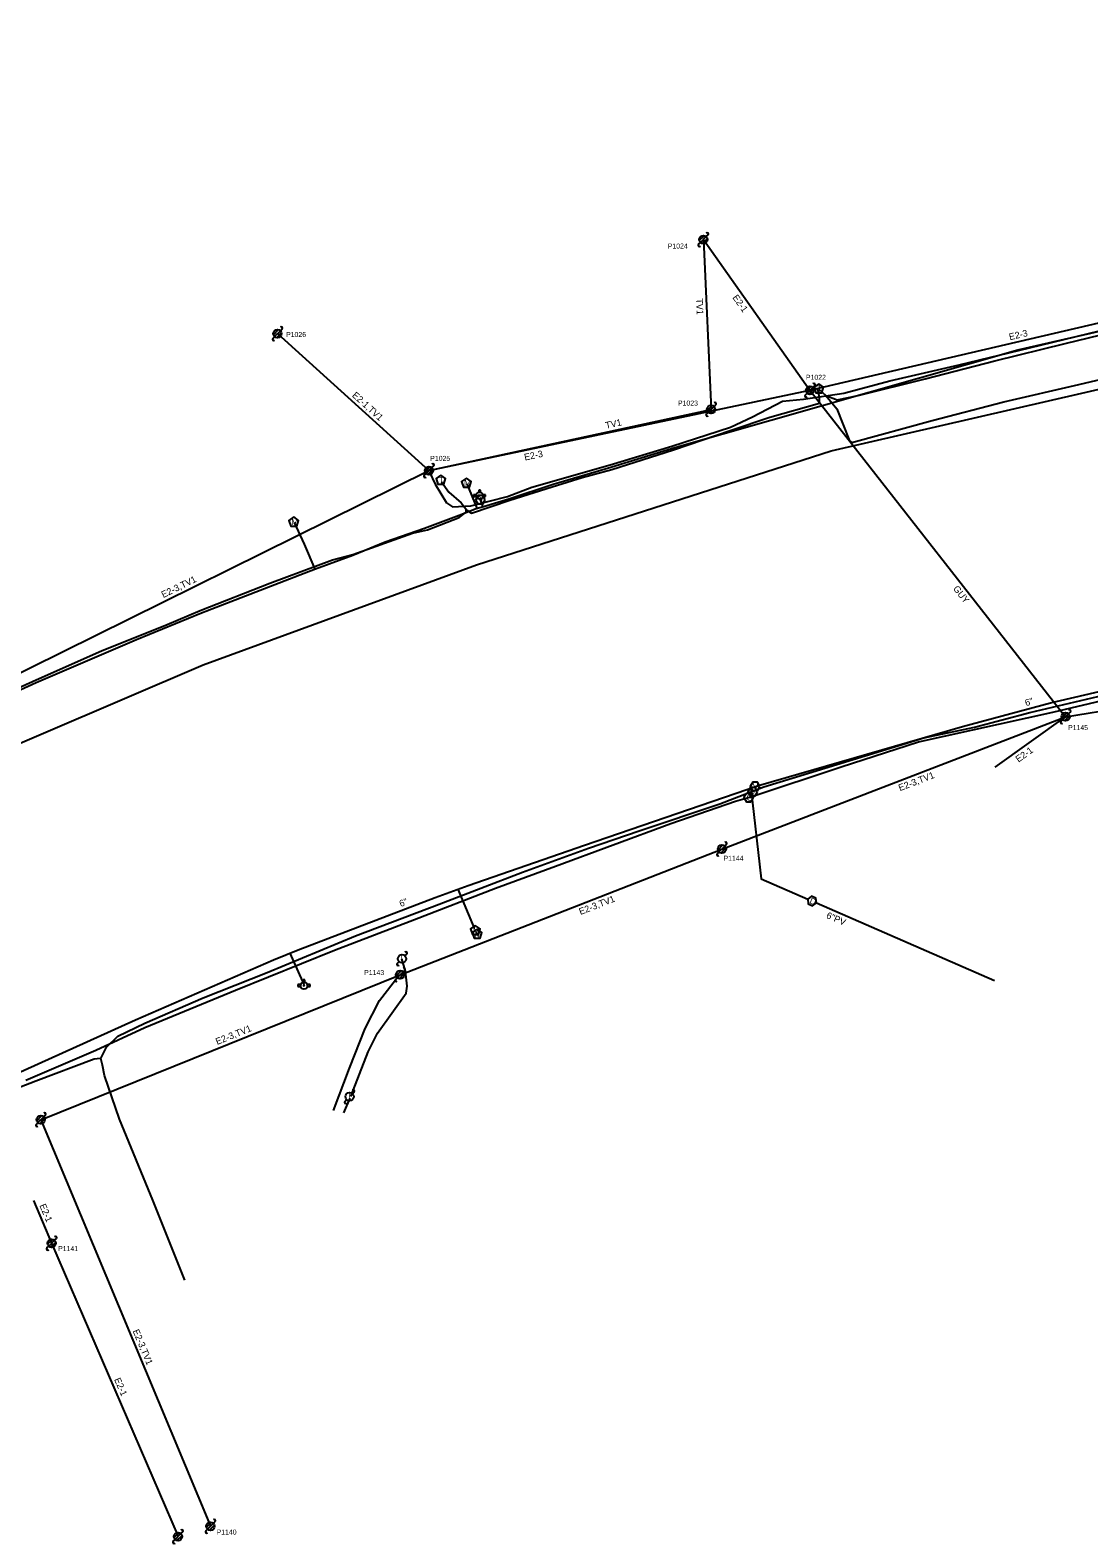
# Model space of a CAD drawing. Extents: x 1614474 to 1865144, y 1098877 to 1212550.
# Drawn here: x 1807205 to 1807840, y 1189319 to 1190224 of the extents above; entities that cross this region are included whole.
import ezdxf

# ---------------------------------------------------------------- set-up
doc = ezdxf.new("R2010")
doc.units = 0
for name, color, linetype in [('BFUSER_FIBERSPAN', 7, 'Continuous'), ('RD_EX_SU_Elec', 7, 'Continuous'), ('RD_EX_SU_Gas', 7, 'Continuous'), ('RD_EX_SU_H2O', 7, 'Continuous'), ('RD_EX_SU_Ovhd', 7, 'Continuous'), ('RD_EX_SU_Pole', 7, 'Continuous'), ('RD_EX_SU_Telecom', 7, 'Continuous'), ('RD_EX_SU_TX_H2O', 7, 'Continuous'), ('RD_EX_SU_TX_Pole', 7, 'Continuous')]:
    doc.layers.add(name, color=color, linetype=linetype)

# ---------------------------------------------------------------- blocks, each defined once
blk = doc.blocks.new('SUE_TPP')
at = {"layer": 'RD_EX_SU_Telecom'}
blk.add_lwpolyline([(0, 3), (-2.85, 0.93), (-1.76, -2.43), (1.76, -2.43), (2.85, 0.93)], close=True, dxfattribs=at)
blk.add_text('T', height=3.75, dxfattribs=at).set_placement((-1.25, -1.88))
blk = doc.blocks.new('SUE_WFH')
at = {"layer": 'RD_EX_SU_H2O'}
for p, q in [((-2.01, 0.6), (-3.65, 0.6)), ((-3.65, 0.6), (-3.65, -0.45)), ((-0.48, 3.38), (-0.48, 2.04)), ((0.57, 3.38), (-0.48, 3.38)), ((0.57, 2.02), (0.57, 3.38)), ((3.7, 0.6), (2.01, 0.6)), ((3.7, -0.45), (3.7, 0.6)), ((-3.65, -0.45), (-2.05, -0.45)), ((2.05, -0.45), (3.7, -0.45))]:
    blk.add_line(p, q, dxfattribs=at)
for radius in [2.1, 0.263]:
    blk.add_circle((0, 0), radius, dxfattribs=at)
for start, end in [(163.3387, 192.31502), (74.24552, 103.21276), (347.68498, 16.6613)]:
    blk.add_arc((0, 0), 2.1, start, end, dxfattribs=at)
blk = doc.blocks.new('SUE_WV')
at = {"layer": 'RD_EX_SU_H2O'}
blk.add_lwpolyline([(2.89, 0), (1.44, 2.5), (-1.44, 2.5), (-2.89, 0), (-1.44, -2.5), (1.44, -2.5)], close=True, dxfattribs=at)
blk.add_text('V', height=3.75, dxfattribs=at).set_placement((-1.43, -1.88))
blk = doc.blocks.new('SUE_WM')
at = {"layer": 'RD_EX_SU_H2O'}
blk.add_lwpolyline([(0, 3.05), (-2.9, 0.94), (-1.79, -2.47), (1.79, -2.47), (2.9, 0.94)], close=True, dxfattribs=at)
blk.add_text('M', height=3.75, dxfattribs=at).set_placement((-1.43, -1.88))
blk = doc.blocks.new('SUE_GVC')
at = {"layer": 'RD_EX_SU_Gas'}
blk.add_lwpolyline([(1.44, -2.5), (2.89, 0), (1.44, 2.5), (-1.44, 2.5), (-2.89, 0), (-1.44, -2.5)], close=True, dxfattribs=at)
blk.add_text('G', height=3.75, dxfattribs=at).set_placement((-1.34, -1.88))
blk = doc.blocks.new('SUE_PP')
at = {"layer": 'RD_EX_SU_Pole'}
for p, q in [((-2.41, -0.65), (0.65, 2.41)), ((-1.77, -1.77), (1.77, 1.77)), ((-0.65, -2.41), (2.41, 0.65)), ((1.77, 1.77), (2.83, 2.83)), ((-2.83, -2.83), (-1.77, -1.77))]:
    blk.add_line(p, q, dxfattribs=at)
blk.add_circle((0, 0), 2.5, dxfattribs=at)
for centre, start, end in [((2.3, 3.36), 315, 135), ((-2.3, -3.36), 135, 315)]:
    blk.add_arc(centre, 0.75, start, end, dxfattribs=at)

msp = doc.modelspace()

# ---------------------------------------------------------------- linework, layer by layer
at = {"layer": 'BFUSER_FIBERSPAN'}
msp.add_lwpolyline([(1805197.46, 1188809.61), (1805749.12, 1189073.42), (1806586.79, 1189481.27), (1806835.69, 1189614.82), (1806952.47, 1189678.93), (1807117.17, 1189761.14), (1807308.95, 1189843.2), (1807472.89, 1189903.24), (1807685.62, 1189971.73), (1807989.14, 1190041.59), (1808242.55, 1190085.58)], dxfattribs=at)
at = {"layer": 'RD_EX_SU_Elec'}
msp.add_line((1807396.79, 1189583.14), (1807393.06, 1189574.26), dxfattribs=at)
for points in [[(1807397.53, 1189584.19), (1807407.84, 1189610.89), (1807413.51, 1189622.09), (1807430.6, 1189646.23), (1807431.32, 1189650.41), (1807430.25, 1189659.4), (1807428, 1189666.79)], [(1807387.03, 1189575.61), (1807396.75, 1189601.17), (1807406.1, 1189624.97), (1807414.64, 1189641.75), (1807426.36, 1189656.68)]]:
    msp.add_lwpolyline(points, dxfattribs=at)
at = {"layer": 'RD_EX_SU_Gas'}
msp.add_lwpolyline([(1807202.55, 1189593.86), (1807244.4, 1189612.02), (1807273.79, 1189625.62), (1807328.26, 1189647.9), (1807387.74, 1189671.88), (1807435.65, 1189690.41), (1807484.25, 1189709.27), (1807520.29, 1189722.4), (1807589.39, 1189747.97), (1807628.2, 1189761.41), (1807638.08, 1189764.18), (1807691.6, 1189781.97), (1807738, 1189797.04), (1807818.59, 1189814.89), (1807892.2, 1189832.29)], dxfattribs=at)
at = {"layer": 'RD_EX_SU_H2O'}
for p, q in [((1807467.01, 1189951.9), (1807473.15, 1189937.24)), ((1807476.63, 1189938.25), (1807475.07, 1189943.77)), ((1807448, 1189703.51), (1807467.81, 1189710.86)), ((1807461.59, 1189708.55), (1807471.51, 1189685.07)), ((1807365.89, 1189672.21), (1807448, 1189703.51)), ((1807351.06, 1189666.17), (1807365.89, 1189672.21)), ((1807360.82, 1189670.14), (1807369.24, 1189651.45))]:
    msp.add_line(p, q, dxfattribs=at)
for points in [[(1807590.47, 1189973.29), (1807797.74, 1190032.28), (1807994.63, 1190077.48)], [(1806907.43, 1189689.88), (1806921.87, 1189696.65), (1806956.44, 1189714.06), (1806994.25, 1189732.8), (1807032.97, 1189751.74), (1807070.31, 1189769.86), (1807107.76, 1189786.85), (1807128.65, 1189797.57), (1807158.71, 1189809.89), (1807208.73, 1189832.68), (1807268.98, 1189858.51), (1807307.86, 1189874.46), (1807369.48, 1189898.22), (1807376.36, 1189900.86), (1807398.77, 1189909.06), (1807418.17, 1189917), (1807441.66, 1189925.38), (1807462.45, 1189933.1), (1807472.72, 1189937.12), (1807477.17, 1189938.4), (1807492.18, 1189942.96), (1807518.95, 1189951.71), (1807553.46, 1189961.82), (1807590.47, 1189973.29)], [(1807363.39, 1189928.67), (1807369.4, 1189915.61), (1807375.83, 1189900.65)], [(1807642.08, 1189770.78), (1807764.43, 1189806.14), (1807817.32, 1189820.38), (1807994.06, 1189861.76), (1808053.5, 1189874.9), (1808100.62, 1189884.58)], [(1807467.81, 1189710.86), (1807537.66, 1189735.05), (1807642.08, 1189770.78)], [(1807637.49, 1189769.21), (1807643.66, 1189714.86), (1807671.58, 1189702.66)], [(1807676.87, 1189700.35), (1807783.7, 1189653.66)], [(1807054.08, 1189530.73), (1807151.37, 1189577.28), (1807268.33, 1189630.19), (1807351.06, 1189666.17)]]:
    msp.add_lwpolyline(points, dxfattribs=at)
msp.add_lwpolyline([(1807676.87, 1189700.35), (1807676.55, 1189703.22), (1807673.91, 1189704.37), (1807671.58, 1189702.66), (1807671.9, 1189699.79), (1807674.55, 1189698.64)], close=True, dxfattribs=at)
at = {"layer": 'RD_EX_SU_Ovhd'}
for p, q in [((1807608.98, 1190098.57), (1807613.61, 1189996.58)), ((1807608.98, 1190098.57), (1807672.95, 1190008.06)), ((1807672.95, 1190008.06), (1807936.63, 1190069.59)), ((1807353.44, 1190042.07), (1807444.37, 1189959.86)), ((1807444.37, 1189959.86), (1807672.95, 1190008.06)), ((1807672.95, 1190008.06), (1807826.32, 1189812.08)), ((1807444.37, 1189959.86), (1807613.61, 1189996.58)), ((1807094.17, 1189786.71), (1807444.37, 1189959.86)), ((1807826.32, 1189812.08), (1808143.68, 1189862.89)), ((1807620.11, 1189732.69), (1807826.32, 1189812.08)), ((1807784.1, 1189781.91), (1807826.32, 1189812.08)), ((1807427.04, 1189657.16), (1807620.11, 1189732.69)), ((1807211.44, 1189570.19), (1807427.04, 1189657.16)), ((1807211.43, 1189570.2), (1807313.24, 1189326.14)), ((1807207.07, 1189521.76), (1807217.98, 1189496.02)), ((1807217.98, 1189496.02), (1807293.8, 1189319.95))]:
    msp.add_line(p, q, dxfattribs=at)
at = {"layer": 'RD_EX_SU_Pole'}
for p, q in [((1807606.56, 1190097.92), (1807609.63, 1190100.99)), ((1807607.21, 1190096.8), (1807610.75, 1190100.34)), ((1807608.33, 1190096.16), (1807611.39, 1190099.22)), ((1807610.75, 1190100.34), (1807611.81, 1190101.4)), ((1807606.15, 1190095.74), (1807607.21, 1190096.8)), ((1807670.53, 1190007.41), (1807673.59, 1190010.48)), ((1807671.18, 1190006.29), (1807674.71, 1190009.83)), ((1807672.3, 1190005.65), (1807675.36, 1190008.71)), ((1807674.71, 1190009.83), (1807675.78, 1190010.89)), ((1807611.19, 1189995.93), (1807614.26, 1189999)), ((1807611.84, 1189994.81), (1807615.38, 1189998.35)), ((1807615.38, 1189998.35), (1807616.44, 1189999.41)), ((1807670.12, 1190005.23), (1807671.18, 1190006.29)), ((1807610.78, 1189993.75), (1807611.84, 1189994.81)), ((1807612.96, 1189994.17), (1807616.02, 1189997.23)), ((1807441.96, 1189959.22), (1807445.02, 1189962.28)), ((1807442.61, 1189958.1), (1807446.14, 1189961.63)), ((1807446.14, 1189961.63), (1807447.2, 1189962.69)), ((1807441.55, 1189957.03), (1807442.61, 1189958.1)), ((1807443.73, 1189957.45), (1807446.79, 1189960.51)), ((1807823.49, 1189809.25), (1807824.55, 1189810.31)), ((1807823.91, 1189811.43), (1807826.97, 1189814.49)), ((1807824.55, 1189810.31), (1807828.09, 1189813.84)), ((1807825.67, 1189809.66), (1807828.74, 1189812.72)), ((1807828.09, 1189813.84), (1807829.15, 1189814.9)), ((1807617.69, 1189732.04), (1807620.75, 1189735.1)), ((1807621.87, 1189734.45), (1807622.94, 1189735.51)), ((1807617.28, 1189729.86), (1807618.34, 1189730.92)), ((1807618.34, 1189730.92), (1807621.87, 1189734.45)), ((1807619.46, 1189730.27), (1807622.52, 1189733.33)), ((1807425.34, 1189664), (1807426.4, 1189665.06)), ((1807429.93, 1189668.6), (1807431, 1189669.66)), ((1807424.21, 1189654.33), (1807425.27, 1189655.39)), ((1807424.63, 1189656.51), (1807427.69, 1189659.57)), ((1807425.27, 1189655.39), (1807428.81, 1189658.93)), ((1807426.39, 1189654.74), (1807429.46, 1189657.81)), ((1807428.81, 1189658.93), (1807429.87, 1189659.99)), ((1807393.88, 1189581.19), (1807394.94, 1189582.25)), ((1807398.47, 1189585.78), (1807399.54, 1189586.84)), ((1807209.02, 1189569.55), (1807212.09, 1189572.61)), ((1807209.67, 1189568.42), (1807213.21, 1189571.96)), ((1807213.21, 1189571.96), (1807214.27, 1189573.02)), ((1807208.61, 1189567.36), (1807209.67, 1189568.42)), ((1807210.79, 1189567.78), (1807213.85, 1189570.84))]:
    msp.add_line(p, q, dxfattribs=at)
for centre in [(1807608.98, 1190098.57), (1807672.95, 1190008.06), (1807613.61, 1189996.58), (1807444.37, 1189959.86), (1807826.32, 1189812.08), (1807620.11, 1189732.69), (1807428.17, 1189666.83), (1807427.04, 1189657.16), (1807396.71, 1189584.02), (1807211.44, 1189570.19)]:
    msp.add_circle(centre, 2.5, dxfattribs=at)
for centre, start, end in [((1807611.28, 1190101.93), 315, 135), ((1807606.68, 1190095.21), 135, 315), ((1807675.25, 1190011.42), 315, 135), ((1807615.91, 1189999.94), 315, 135), ((1807670.65, 1190004.7), 135, 315), ((1807611.31, 1189993.22), 135, 315), ((1807446.67, 1189963.22), 315, 135), ((1807442.08, 1189956.5), 135, 315), ((1807824.02, 1189808.72), 135, 315), ((1807828.62, 1189815.43), 315, 135), ((1807622.41, 1189736.04), 315, 135), ((1807617.81, 1189729.33), 135, 315), ((1807425.87, 1189663.47), 135, 315), ((1807430.47, 1189670.19), 315, 135), ((1807424.74, 1189653.8), 135, 315), ((1807429.34, 1189660.52), 315, 135), ((1807394.41, 1189580.66), 135, 315), ((1807399, 1189587.38), 315, 135), ((1807213.74, 1189573.55), 315, 135), ((1807209.14, 1189566.83), 135, 315)]:
    msp.add_arc(centre, 0.75, start, end, dxfattribs=at)
at = {"layer": 'RD_EX_SU_Telecom'}
for points in [[(1807682.5, 1190004.86), (1807689.27, 1190002.32), (1807701.89, 1190004.93), (1807742.09, 1190014.9), (1807783.79, 1190025.79), (1807826.14, 1190036.18), (1807889.51, 1190051.54), (1807953.85, 1190065.04), (1807974.32, 1190070.37), (1808007.49, 1190077.56), (1808013.57, 1190081.16), (1808017.43, 1190089.5), (1808027.32, 1190095.12), (1808028.05, 1190096.96), (1808027.78, 1190101.02), (1808023.46, 1190126.79), (1808016.98, 1190164.5), (1808006.98, 1190224.27)], [(1807678.17, 1190008.71), (1807682.41, 1190004.96), (1807689.11, 1189996.9), (1807696.72, 1189977.75), (1807698.02, 1189976.79), (1807746.2, 1189989.96), (1807789.33, 1190001.12), (1807834.33, 1190011.55), (1807879.26, 1190022.08), (1807923.16, 1190032.03), (1807967.55, 1190041.17), (1807996.6, 1190043.46), (1808016.06, 1190044.83), (1808064.17, 1190052.82), (1808135.81, 1190066.49), (1808175.72, 1190072.55), (1808208.14, 1190077.12), (1808224.34, 1190077.5), (1808234.29, 1190073.69)], [(1807444.75, 1189958.89), (1807448.07, 1189951.74), (1807454.82, 1189940.47), (1807458.49, 1189938.01), (1807469.49, 1189938.8), (1807491.5, 1189944.36), (1807506.12, 1189949.89), (1807553.11, 1189963.22), (1807590.09, 1189974.45), (1807625.17, 1189985.92), (1807638.41, 1189992.04), (1807656.49, 1190001.48), (1807669.1, 1190002.7), (1807693.36, 1190006.35), (1807720.9, 1190013.74), (1807762.38, 1190023.34), (1807804.67, 1190033.56), (1807846.62, 1190043.84)], [(1807451.92, 1189953.19), (1807456.24, 1189946.99), (1807463.77, 1189940.51), (1807467.13, 1189936.05), (1807469.88, 1189934.36), (1807492.87, 1189942.01), (1807518.24, 1189950.04), (1807536.2, 1189955.64), (1807553.99, 1189960.56), (1807591.02, 1189972.35), (1807625.75, 1189984.05), (1807648.79, 1189991.89), (1807678.57, 1190000.25), (1807678.72, 1190003.76), (1807677.75, 1190008.65)], [(1806904.55, 1189692.54), (1806906.54, 1189692.06), (1806920.67, 1189698.38), (1806940.27, 1189707.91), (1806972.42, 1189723.75), (1807010.25, 1189742.6), (1807051.28, 1189762.56), (1807089.91, 1189780.61), (1807119.1, 1189796.65), (1807136.71, 1189803.97), (1807145.05, 1189805.3), (1807173.1, 1189818.28), (1807208.66, 1189834.24), (1807247.85, 1189851.63), (1807287.35, 1189867.48), (1807307.05, 1189875.88), (1807348.87, 1189892.28), (1807386.47, 1189906.36), (1807398.63, 1189909.48), (1807434.55, 1189922.3), (1807443.51, 1189924.38), (1807462.38, 1189931.66), (1807466.63, 1189934.89), (1807466.75, 1189936.55)], [(1807297.92, 1189473.8), (1807278.62, 1189521.83), (1807258.78, 1189570.48), (1807249.72, 1189596.68), (1807248.4, 1189603), (1807247.52, 1189606.94), (1807250.87, 1189613.72), (1807257.72, 1189620.43), (1807273.89, 1189628.12), (1807308.81, 1189643.37), (1807347.37, 1189658.6), (1807400.32, 1189680.47), (1807450.38, 1189699.52), (1807500.38, 1189718.76), (1807540.17, 1189733.15), (1807570.54, 1189743.69), (1807618.79, 1189759.82), (1807645.17, 1189770.03), (1807671.99, 1189778.24), (1807705.97, 1189788.55), (1807741.2, 1189799.36), (1807771.63, 1189805.79), (1807804.88, 1189814.7), (1807852.38, 1189825.77)], [(1807003.98, 1189490.66), (1807002.64, 1189495.29), (1807002.36, 1189497.76), (1807009.44, 1189502.95), (1807050.21, 1189525.6), (1807090.24, 1189545.85), (1807128.99, 1189564.14), (1807166.58, 1189577.34), (1807208.43, 1189593.43), (1807243.47, 1189606.68), (1807247.15, 1189607.1), (1807247.52, 1189606.94)]]:
    msp.add_lwpolyline(points, dxfattribs=at)

# ---------------------------------------------------------------- block references
at = {"layer": 'RD_EX_SU_Gas'}
msp.add_blockref('SUE_GVC', (1807636.22, 1189763.59), dxfattribs=at)
at = {"layer": 'RD_EX_SU_H2O'}
for name, p in [('SUE_WM', (1807466.86, 1189952.31)), ('SUE_WFH', (1807474.66, 1189944.8)), ('SUE_WV', (1807475.2, 1189942.34)), ('SUE_WM', (1807363.21, 1189928.99)), ('SUE_WV', (1807640.03, 1189770.3)), ('SUE_WV', (1807638.64, 1189767.11)), ('SUE_WM', (1807472.17, 1189683.77)), ('SUE_WM', (1807473.24, 1189681.58)), ('SUE_WFH', (1807369.37, 1189650.68))]:
    msp.add_blockref(name, p, dxfattribs=at)
at = {"layer": 'RD_EX_SU_Pole'}
for p in [(1807353.44, 1190042.07), (1807217.98, 1189496.02), (1807313.24, 1189326.14), (1807293.8, 1189319.95)]:
    msp.add_blockref('SUE_PP', p, dxfattribs=at)
at = {"layer": 'RD_EX_SU_Telecom'}
for p in [(1807678.29, 1190009), (1807451.43, 1189954.16)]:
    msp.add_blockref('SUE_TPP', p, dxfattribs=at)

# ---------------------------------------------------------------- texts
at = {"layer": 'RD_EX_SU_H2O'}
msp.add_text('D', height=3.75, rotation=336.39121, dxfattribs=at).set_placement((1807672.33, 1189700.29))
at = {"layer": 'RD_EX_SU_Ovhd'}
for s, rotation, p in [('TV1', 272.59909, (1807604.58, 1190063.13)), ('E2-1', 305.25127, (1807626.25, 1190063.73)), ('E2-3', 13.13504, (1807792.88, 1190038.1)), ('E2-1,TV1', 317.88404, (1807397.9, 1190004.57)), ('TV1', 12.24145, (1807550.65, 1189984.97)), ('E2-3', 11.90739, (1807501.95, 1189965.87)), ('E2-3,TV1', 26.30911, (1807284.98, 1189883.29)), ('GUY', 308.04587, (1807758.59, 1189888.89)), ('E2-1', 35.54511, (1807798.07, 1189784.52)), ('E2-3,TV1', 21.05602, (1807726.92, 1189767.38)), ('E2-3,TV1', 21.36524, (1807535.27, 1189693.06)), ('E2-3,TV1', 21.96753, (1807317.31, 1189615.05)), ('E2-1', 292.96138, (1807210.54, 1189518.7)), ('E2-3,TV1', 292.64376, (1807266.5, 1189443.37)), ('E2-1', 293.29789, (1807255.38, 1189414.23))]:
    msp.add_text(s, height=4, rotation=rotation, dxfattribs=at).set_placement(p)
at = {"layer": 'RD_EX_SU_Pole'}
for p in [(1807427.3, 1189664.83), (1807395.84, 1189582.02)]:
    msp.add_text('L', height=4, dxfattribs=at).set_placement(p)
at = {"layer": 'RD_EX_SU_TX_H2O'}
for s, rotation, p in [('6"', 15.07555, (1807802.54, 1189818.47)), ('6"', 20.87049, (1807427.46, 1189697.82)), ('6"PV', 336.39121, (1807682.36, 1189691.4))]:
    msp.add_text(s, height=4, rotation=rotation, dxfattribs=at).set_placement(p)
at = {"layer": 'RD_EX_SU_TX_Pole'}
for s, p in [('P1024', (1807587.64, 1190093.18)), ('P1026', (1807358.63, 1190040.05)), ('P1022', (1807670.54, 1190014.37)), ('P1023', (1807593.76, 1189998.89)), ('P1025', (1807445.12, 1189965.7)), ('P1145', (1807827.82, 1189804.08)), ('P1144', (1807621.09, 1189725.63)), ('P1143', (1807405.5, 1189657.03)), ('P1141', (1807221.87, 1189491.31)), ('P1140', (1807316.94, 1189321.14))]:
    msp.add_text(s, height=3, dxfattribs=at).set_placement(p)

doc.saveas('drawing.dxf')
